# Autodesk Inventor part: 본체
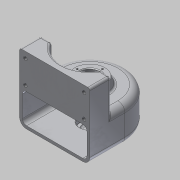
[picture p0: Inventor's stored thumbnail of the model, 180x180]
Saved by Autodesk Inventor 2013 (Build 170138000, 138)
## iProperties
Created: 2015-02
Part Number: 본체
Material: 알루미늄 6061
Document SubType Name: Modeling
Designer: Administrator
Density: 2.71 g/cm^3
Mass: 519.169 g
Surface Area: 717.843 cm^2
Volume: 191.575 cm^3
Author: Administrator
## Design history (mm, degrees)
sketch "스케치1"
  geometry: L1 (-50, -50)-(50, -50); L2 (50, -50)-(50, 0); L3 (-50, -50)-(-50, 0); A1 r 50 centre (0, 0) between (50, 0) and (-50, 0); 2 further points
  constraints: 6 end point, 2 midpoint, 2 point on circle, 2 tangent, 2 vertical, 1 centre point, 1 coincident, 1 horizontal, 1 vertical alignment
  dimensions: "d0" = 100 diameter of A1; "d1" = 50 distance from line of point (0, 0) L1
extrude "돌출1" new body sketch "스케치1" stored distance "d2" = 50; taper "d3" = 0 deg
sketch "스케치2"
  geometry: L1 (50, -50)-(-50, -50) reference; L2 (-50, -50)-(-50, 0) reference; L3 (50, 0)-(50, -50) reference; L4 (-46, 0)-(-46, -50); L5 (46, 0)-(46, -50); A1 r 50 centre (0, 0) between (50, 0) and (-50, 0) reference; A2 r 46 centre (0, 0) between (46, 0) and (-46, 0); 1 further point
  constraints: 4 end point, 2 perpendicular, 2 point on circle, 2 point on line, 2 tangent, 1 centre point, 1 coincident
  dimensions: "d4" = 92 diameter of A2
extrude "돌출2" cut sketch "스케치2" stored distance "d5" = 42; taper "d6" = 0 deg
sketch "스케치3"
  geometry: L1 (-50, -50)-(50, -50) reference; L2 (-50, -50)-(50, -50) reference; L3 (50, -50)-(50, 0) reference; L4 (-50, 0)-(-50, -50) reference; L5 (-50, -50)-(50, -50); L6 (50, -50)-(50, -20); L7 (50, -20)-(34.641, -20); L8 (-50, -50)-(-50, -20); L9 (-50, -20)-(-34.641, -20); A1 r 50 centre (0, 0) between (50, 0) and (-50, 0) reference; A2 r 40 centre (0, 0) between (-34.641, -20) and (34.641, -20)
  constraints: 10 end point, 2 collinear, 2 perpendicular, 2 point on circle, 2 point on line, 1 centre point, 1 coincident
  dimensions: "d7" = 80 diameter of A2; "d8" = 30 distance between parallel lines of L1 L7
extrude "돌출3" join sketch "스케치3" distance "d9" = 45; taper "d10" = 0 deg
sketch "스케치4"
  geometry: C1 r 25 at (0, 0); A1 r 40 centre (0, 0) between (-34.641, -20) and (34.641, -20) reference
  constraints: 1 centre point, 1 coincident
  dimensions: "d11" = 50 diameter of C1
extrude "돌출4" join sketch "스케치4" distance "d12" = 10; taper "d13" = 0 deg
hole "구멍1" diameter "d16" = 20; stored, may be unused: countersink angle "d20" = 90 deg, drill point angle "d22" = 118 deg; dims "d14" = 10, "d15" = 10, "d17" = 6, "d18" = 28, "d19" = 10, "d21" = 28.75
feature "면 기울기1" dims angle "d23" = 20 deg
sketch "스케치5"
  geometry: C1 r 20 at (0, 0); A1 r 50 centre (0, 0) between (50, 0) and (-50, 0) reference
  constraints: 1 centre point, 1 coincident
  dimensions: "d24" = 40 diameter of C1
extrude "돌출5" join sketch "스케치5" distance "d26" = 9; taper "d27" = 0 deg
hole "구멍2" diameter "d30" = 20; stored, may be unused: countersink angle "d34" = 90 deg, drill point angle "d36" = 0 deg; dims "d28" = 10, "d29" = 10, "d31" = 6, "d32" = 28, "d33" = 8, "d35" = 10
sketch "스케치6"
  geometry: C1 r 14 at (0, 0) reference; 1 further point
  constraints: 1 vertical alignment
  dimensions: "d37" = 18 distance of point (0, 18) C1.centre
hole "구멍3" sketch "스케치6" at (0, 18) diameter "d38" = 2.459; stored, may be unused: countersink angle "d42" = 90 deg, drill point angle "d44" = 118 deg; dims "d39" = 6, "d40" = 28, "d41" = 8, "d43" = 9
sketch "스케치7"
  geometry: L1 (100, 0)-(100, 95) reference; L2 (0, 95)-(100, 95) reference; 5 further points
  constraints: 2 horizontal alignment, 2 vertical alignment
  dimensions: "d49" = 9 distance from line of L2 point (91.75, 86); "d50" = 33 distance of point (91.75, 53) point (91.75, 86); "d51" = 83.5 distance of point (8.25, 86) point (91.75, 86); "d52" = 8.25 distance from line of point (91.75, 86) L1
hole "구멍4" sketch "스케치7" at (91.75, 86), (91.75, 53), (8.25, 86), (8.25, 53) diameter "d53" = 5.134; stored, may be unused: countersink angle "d57" = 90 deg, drill point angle "d59" = 118 deg; dims "d54" = 10, "d55" = 28, "d56" = 8, "d58" = 13
fillet "모깎기1" dims "d60" = 6, "d61" = 10
fillet "모깎기2" dims "d62" = 0.3
fillet "모깎기3" dims "d63" = 3
fillet "모깎기4" dims "d64" = 3
chamfer "모따기1" distance "d65" = 1; stored, may be unused: second distance "d66" = 2, angle "d67" = 45 deg
node "작업 평면1"
sketch "스케치8"
  geometry: L1 (40, -25)-(-40, -25) reference; 2 further points
  constraints: 1 coincident, 1 other
  dimensions: "d68" = 25 distance from line of point (0, 0) L1
feature "엠보싱1" sketch "스케치8" dims "d0" = 100, "d1" = 50, "d69" = 0.5, "d70" = 0
fillet "모깎기5" dims "d71" = 3
node "솔리드1"
pattern_circular "원형 패턴1" dims angle "d46" = 360 deg
node "투영된 루프1"
node "투영된 루프2"
